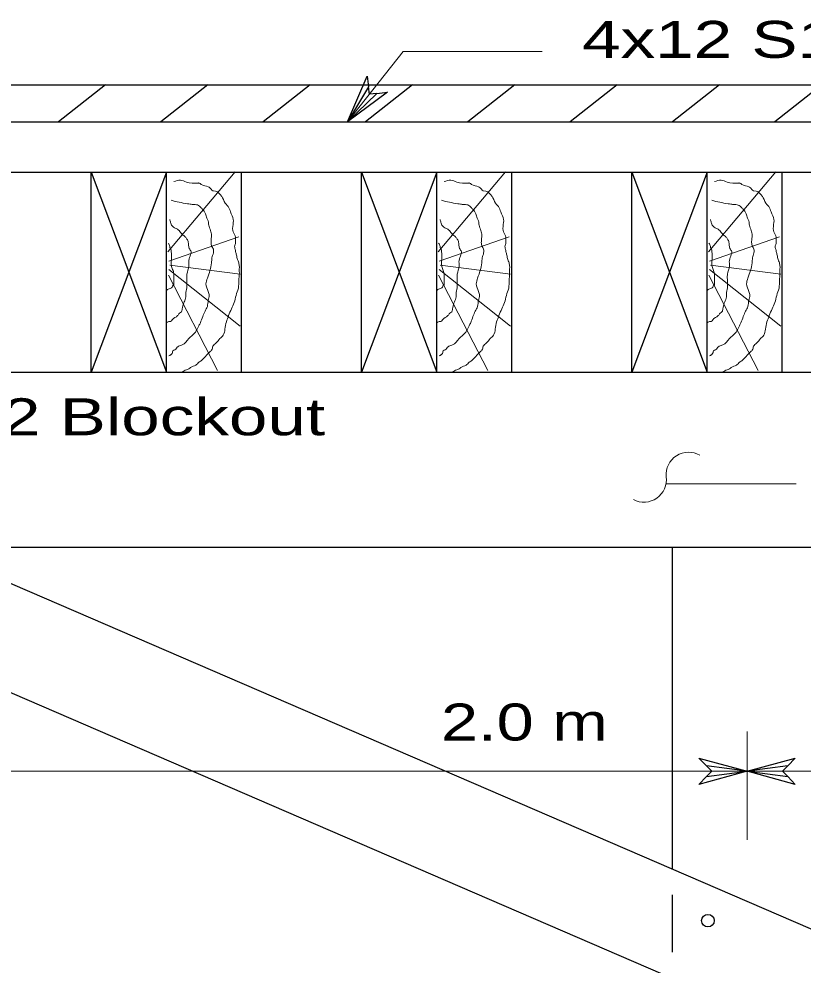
# Model space of a CAD drawing. Extents: x 13426 to 15509, y -9298 to -5111.
# Drawn here: x 15384.27 to 15412, y -5426.77 to -5393.3 of the extents above; entities that cross this region are included whole.
import ezdxf
from ezdxf.enums import TextEntityAlignment as Align

# ---------------------------------------------------------------- set-up
doc = ezdxf.new("R2010")
doc.units = 0
doc.header["$LTSCALE"] = 0.52
for name, color, linetype, lineweight in [('1', 7, 'Continuous', 13), ('15', 7, 'Continuous', 13), ('16', 7, 'Continuous', 25), ('2', 7, 'Continuous', 25), ('20', 7, 'Continuous', 13), ('4', 7, 'Continuous', 13)]:
    doc.layers.add(name, color=color, linetype=linetype, lineweight=lineweight)
doc.layers.add('19', color=7, linetype='Continuous')

msp = doc.modelspace()

# ---------------------------------------------------------------- linework, layer by layer
at = {"layer": '1', "lineweight": 25}
for p, q in [((15363.992, -5405.801), (15491.456, -5405.801)), ((15491.456, -5411.997), (15381.02, -5411.997)), ((15407.365, -5411.997), (15407.365, -5423.373)), ((15407.365, -5424.286), (15407.365, -5426.316))]:
    msp.add_line(p, q, dxfattribs=at)
at = {"layer": '1'}
for p, q in [((15410.021, -5418.508), (15410.021, -5422.337)), ((15374.614, -5419.918), (15410.021, -5419.918))]:
    msp.add_line(p, q, dxfattribs=at)
msp.add_lwpolyline([(15410.021, -5419.918), (15427.724, -5419.918), (15445.428, -5419.918)], dxfattribs=at)
at = {"layer": '15'}
msp.add_line((15407.154, -5409.744), (15411.753, -5409.744), dxfattribs=at)
msp.add_lwpolyline([(15395.887, -5396.949), (15397.859, -5394.453), (15402.777, -5394.453)], dxfattribs=at)
for centre, start, end in [((15407.9489, -5409.4258), 59.84377, 185.31451), ((15406.3728, -5409.6049), 242.17771, 7.64844)]:
    msp.add_arc(centre, 0.7933, start, end, dxfattribs=at)
at = {"layer": '16'}
for points in [[(15396.926, -5395.937), (15397.308, -5395.9), (15395.887, -5396.949), (15396.579, -5395.324), (15396.631, -5395.704), (15395.887, -5396.949), (15396.926, -5395.937), (15396.662, -5395.968), (15396.631, -5395.704)], [(15408.582, -5419.73), (15408.317, -5419.454), (15410.021, -5419.918), (15408.317, -5420.383), (15408.582, -5420.106), (15410.021, -5419.918), (15408.582, -5419.73), (15408.77, -5419.918), (15408.582, -5420.106)], [(15411.459, -5420.106), (15411.725, -5420.383), (15410.021, -5419.918), (15411.725, -5419.454), (15411.459, -5419.73), (15410.021, -5419.918), (15411.459, -5420.106), (15411.271, -5419.918), (15411.459, -5419.73)]]:
    msp.add_lwpolyline(points, dxfattribs=at)
at = {"layer": '2'}
for p, q in [((15366.672, -5405.801), (15490.937, -5459.463)), ((15365.268, -5409.051), (15489.534, -5462.713))]:
    msp.add_line(p, q, dxfattribs=at)
msp.add_circle((15408.6347, -5425.2011), 0.2213, dxfattribs=at)
at = {"layer": '4', "lineweight": 25}
for p, q in [((15368.805, -5395.631), (15486.643, -5395.631)), ((15387.328, -5395.631), (15385.671, -5396.949)), ((15390.947, -5395.631), (15389.29, -5396.949)), ((15394.567, -5395.631), (15392.91, -5396.949)), ((15398.186, -5395.631), (15396.529, -5396.949)), ((15401.806, -5395.631), (15400.149, -5396.949)), ((15405.425, -5395.631), (15403.768, -5396.949)), ((15409.044, -5395.631), (15407.388, -5396.949)), ((15412.664, -5395.631), (15411.007, -5396.949)), ((15369.303, -5398.72), (15486.145, -5398.72)), ((15386.829, -5405.801), (15386.829, -5398.72)), ((15386.829, -5398.72), (15389.485, -5405.801)), ((15389.485, -5398.72), (15386.829, -5405.801)), ((15389.485, -5405.801), (15389.485, -5398.72)), ((15392.14, -5405.801), (15392.14, -5398.72)), ((15396.389, -5405.801), (15396.389, -5398.72)), ((15396.389, -5398.72), (15399.045, -5405.801)), ((15399.045, -5398.72), (15396.389, -5405.801)), ((15399.045, -5405.801), (15399.045, -5398.72)), ((15401.7, -5405.801), (15401.7, -5398.72)), ((15405.949, -5405.801), (15405.949, -5398.72)), ((15405.949, -5398.72), (15408.604, -5405.801)), ((15408.604, -5398.72), (15405.949, -5405.801)), ((15408.604, -5405.801), (15408.604, -5398.72)), ((15411.26, -5405.801), (15411.26, -5398.72))]:
    msp.add_line(p, q, dxfattribs=at)
at = {"layer": '4'}
for p, q in [((15391.916, -5398.719), (15389.537, -5401.539)), ((15401.475, -5398.719), (15399.097, -5401.539)), ((15411.035, -5398.719), (15408.657, -5401.539)), ((15392.047, -5401.013), (15389.57, -5401.879)), ((15401.607, -5401.013), (15399.13, -5401.879)), ((15411.167, -5401.013), (15408.69, -5401.879)), ((15392.096, -5402.337), (15389.603, -5402.015)), ((15401.656, -5402.337), (15399.163, -5402.015)), ((15411.216, -5402.337), (15408.722, -5402.015)), ((15391.292, -5405.735), (15389.553, -5402.372)), ((15392.096, -5404.172), (15389.57, -5402.168)), ((15400.852, -5405.735), (15399.113, -5402.372)), ((15401.656, -5404.172), (15399.13, -5402.168)), ((15410.412, -5405.735), (15408.673, -5402.372)), ((15411.216, -5404.172), (15408.69, -5402.168))]:
    msp.add_line(p, q, dxfattribs=at)
at = {"layer": '4', "lineweight": 25}
msp.add_lwpolyline([(15369.303, -5396.949), (15486.145, -5396.949), (15486.145, -5405.801)], dxfattribs=at)
at = {"layer": '4'}
for points in [[(15389.75, -5399.059), (15389.98, -5399.008), (15390.193, -5399.076), (15390.603, -5399.109), (15390.636, -5399.109), (15390.718, -5399.161), (15390.964, -5399.245), (15391.063, -5399.33), (15391.128, -5399.382), (15391.145, -5399.382), (15391.407, -5399.534), (15391.473, -5399.636), (15391.604, -5399.874), (15391.67, -5399.942), (15391.752, -5400.129), (15391.85, -5400.401), (15391.85, -5400.503), (15391.834, -5400.791), (15391.916, -5400.979), (15391.932, -5401.149), (15391.916, -5401.284), (15391.899, -5401.335), (15391.899, -5401.386), (15391.916, -5401.454), (15391.932, -5401.539), (15391.965, -5401.658), (15391.981, -5401.743), (15392.03, -5401.896), (15392.063, -5402.032), (15392.063, -5402.151), (15392.063, -5402.337), (15392.047, -5402.542), (15392.03, -5402.83), (15391.948, -5403.085), (15391.883, -5403.34), (15391.784, -5403.561), (15391.686, -5403.799), (15391.604, -5404.019), (15391.555, -5404.274), (15391.489, -5404.495), (15391.375, -5404.614), (15391.243, -5404.767), (15391.128, -5404.886), (15391.112, -5404.954), (15391.079, -5405.022), (15391.014, -5405.09), (15390.915, -5405.192), (15390.833, -5405.277), (15390.735, -5405.379), (15390.636, -5405.447), (15390.521, -5405.549), (15390.341, -5405.634), (15390.275, -5405.685), (15390.193, -5405.719), (15390.111, -5405.753), (15389.964, -5405.804), (15389.962, -5405.804)], [(15399.31, -5399.059), (15399.54, -5399.008), (15399.753, -5399.076), (15400.163, -5399.109), (15400.196, -5399.109), (15400.278, -5399.161), (15400.524, -5399.245), (15400.622, -5399.33), (15400.688, -5399.382), (15400.704, -5399.382), (15400.967, -5399.534), (15401.032, -5399.636), (15401.164, -5399.874), (15401.229, -5399.942), (15401.311, -5400.129), (15401.41, -5400.401), (15401.41, -5400.503), (15401.393, -5400.791), (15401.475, -5400.979), (15401.492, -5401.149), (15401.475, -5401.284), (15401.459, -5401.335), (15401.459, -5401.386), (15401.475, -5401.454), (15401.492, -5401.539), (15401.525, -5401.658), (15401.541, -5401.743), (15401.59, -5401.896), (15401.623, -5402.032), (15401.623, -5402.151), (15401.623, -5402.337), (15401.607, -5402.542), (15401.59, -5402.83), (15401.508, -5403.085), (15401.443, -5403.34), (15401.344, -5403.561), (15401.246, -5403.799), (15401.164, -5404.019), (15401.115, -5404.274), (15401.049, -5404.495), (15400.934, -5404.614), (15400.803, -5404.767), (15400.688, -5404.886), (15400.672, -5404.954), (15400.639, -5405.022), (15400.573, -5405.09), (15400.475, -5405.192), (15400.393, -5405.277), (15400.295, -5405.379), (15400.196, -5405.447), (15400.081, -5405.549), (15399.901, -5405.634), (15399.835, -5405.685), (15399.753, -5405.719), (15399.671, -5405.753), (15399.523, -5405.804), (15399.522, -5405.804)], [(15408.87, -5399.059), (15409.1, -5399.008), (15409.313, -5399.076), (15409.723, -5399.109), (15409.756, -5399.109), (15409.838, -5399.161), (15410.084, -5399.245), (15410.182, -5399.33), (15410.248, -5399.382), (15410.264, -5399.382), (15410.527, -5399.534), (15410.592, -5399.636), (15410.724, -5399.874), (15410.789, -5399.942), (15410.871, -5400.129), (15410.97, -5400.401), (15410.97, -5400.503), (15410.953, -5400.791), (15411.035, -5400.979), (15411.052, -5401.149), (15411.035, -5401.284), (15411.019, -5401.335), (15411.019, -5401.386), (15411.035, -5401.454), (15411.052, -5401.539), (15411.084, -5401.658), (15411.101, -5401.743), (15411.15, -5401.896), (15411.183, -5402.032), (15411.183, -5402.151), (15411.183, -5402.337), (15411.167, -5402.542), (15411.15, -5402.83), (15411.068, -5403.085), (15411.003, -5403.34), (15410.904, -5403.561), (15410.806, -5403.799), (15410.724, -5404.019), (15410.674, -5404.274), (15410.609, -5404.495), (15410.494, -5404.614), (15410.363, -5404.767), (15410.248, -5404.886), (15410.231, -5404.954), (15410.199, -5405.022), (15410.133, -5405.09), (15410.035, -5405.192), (15409.953, -5405.277), (15409.854, -5405.379), (15409.756, -5405.447), (15409.641, -5405.549), (15409.461, -5405.634), (15409.395, -5405.685), (15409.313, -5405.719), (15409.231, -5405.753), (15409.083, -5405.804), (15409.082, -5405.804)], [(15389.652, -5399.721), (15389.931, -5399.789), (15390.226, -5399.84), (15390.325, -5399.857), (15390.456, -5399.874), (15390.505, -5399.874), (15390.653, -5399.925), (15390.669, -5399.942), (15390.751, -5400.027), (15390.866, -5400.197), (15390.915, -5400.35), (15390.964, -5400.452), (15390.981, -5400.605), (15391.046, -5400.791), (15391.079, -5400.961), (15391.063, -5401.182), (15391.079, -5401.318), (15391.145, -5401.454), (15391.145, -5401.573), (15391.096, -5401.76), (15391.079, -5401.93), (15390.932, -5402.473), (15390.882, -5402.677), (15390.964, -5402.949), (15390.997, -5403.085), (15390.964, -5403.255), (15390.932, -5403.476), (15390.85, -5403.646), (15390.768, -5403.833), (15390.685, -5404.053), (15390.636, -5404.156), (15390.538, -5404.343), (15390.407, -5404.495), (15390.275, -5404.614), (15390.046, -5404.835), (15389.98, -5404.852), (15389.914, -5404.886), (15389.865, -5404.92), (15389.816, -5404.988), (15389.701, -5405.073), (15389.701, -5405.107), (15389.652, -5405.175), (15389.635, -5405.192), (15389.57, -5405.226)], [(15399.212, -5399.721), (15399.491, -5399.789), (15399.786, -5399.84), (15399.884, -5399.857), (15400.016, -5399.874), (15400.065, -5399.874), (15400.213, -5399.925), (15400.229, -5399.942), (15400.311, -5400.027), (15400.425, -5400.197), (15400.475, -5400.35), (15400.524, -5400.452), (15400.541, -5400.605), (15400.606, -5400.791), (15400.639, -5400.961), (15400.622, -5401.182), (15400.639, -5401.318), (15400.704, -5401.454), (15400.704, -5401.573), (15400.655, -5401.76), (15400.639, -5401.93), (15400.491, -5402.473), (15400.442, -5402.677), (15400.524, -5402.949), (15400.557, -5403.085), (15400.524, -5403.255), (15400.491, -5403.476), (15400.409, -5403.646), (15400.327, -5403.833), (15400.245, -5404.053), (15400.196, -5404.156), (15400.098, -5404.343), (15399.966, -5404.495), (15399.835, -5404.614), (15399.606, -5404.835), (15399.54, -5404.852), (15399.474, -5404.886), (15399.425, -5404.92), (15399.376, -5404.988), (15399.261, -5405.073), (15399.261, -5405.107), (15399.212, -5405.175), (15399.195, -5405.192), (15399.13, -5405.226)], [(15408.772, -5399.721), (15409.051, -5399.789), (15409.346, -5399.84), (15409.444, -5399.857), (15409.575, -5399.874), (15409.625, -5399.874), (15409.772, -5399.925), (15409.789, -5399.942), (15409.871, -5400.027), (15409.985, -5400.197), (15410.035, -5400.35), (15410.084, -5400.452), (15410.101, -5400.605), (15410.166, -5400.791), (15410.199, -5400.961), (15410.182, -5401.182), (15410.199, -5401.318), (15410.264, -5401.454), (15410.264, -5401.573), (15410.215, -5401.76), (15410.199, -5401.93), (15410.051, -5402.473), (15410.002, -5402.677), (15410.084, -5402.949), (15410.117, -5403.085), (15410.084, -5403.255), (15410.051, -5403.476), (15409.969, -5403.646), (15409.887, -5403.833), (15409.805, -5404.053), (15409.756, -5404.156), (15409.658, -5404.343), (15409.526, -5404.495), (15409.395, -5404.614), (15409.165, -5404.835), (15409.1, -5404.852), (15409.034, -5404.886), (15408.985, -5404.92), (15408.936, -5404.988), (15408.821, -5405.073), (15408.821, -5405.107), (15408.772, -5405.175), (15408.755, -5405.192), (15408.69, -5405.226)], [(15389.603, -5400.401), (15389.635, -5400.503), (15389.685, -5400.622), (15389.8, -5400.706), (15389.849, -5400.724), (15389.931, -5400.791), (15390.046, -5400.928), (15390.144, -5401.013), (15390.21, -5401.097), (15390.259, -5401.199), (15390.292, -5401.42), (15390.357, -5401.539), (15390.341, -5401.641), (15390.275, -5401.845), (15390.275, -5402.049), (15390.21, -5402.337), (15390.21, -5402.762), (15390.177, -5402.983), (15390.161, -5403.187), (15390.095, -5403.357), (15390.046, -5403.561), (15390.013, -5403.663), (15389.947, -5403.714), (15389.882, -5403.799), (15389.685, -5403.952), (15389.635, -5404.003), (15389.603, -5404.003), (15389.488, -5404.053)], [(15399.163, -5400.401), (15399.195, -5400.503), (15399.245, -5400.622), (15399.359, -5400.706), (15399.409, -5400.724), (15399.491, -5400.791), (15399.606, -5400.928), (15399.704, -5401.013), (15399.77, -5401.097), (15399.819, -5401.199), (15399.852, -5401.42), (15399.917, -5401.539), (15399.901, -5401.641), (15399.835, -5401.845), (15399.835, -5402.049), (15399.77, -5402.337), (15399.77, -5402.762), (15399.737, -5402.983), (15399.72, -5403.187), (15399.655, -5403.357), (15399.606, -5403.561), (15399.573, -5403.663), (15399.507, -5403.714), (15399.441, -5403.799), (15399.245, -5403.952), (15399.195, -5404.003), (15399.163, -5404.003), (15399.048, -5404.053)], [(15408.722, -5400.401), (15408.755, -5400.503), (15408.804, -5400.622), (15408.919, -5400.706), (15408.969, -5400.724), (15409.051, -5400.791), (15409.165, -5400.928), (15409.264, -5401.013), (15409.329, -5401.097), (15409.379, -5401.199), (15409.411, -5401.42), (15409.477, -5401.539), (15409.461, -5401.641), (15409.395, -5401.845), (15409.395, -5402.049), (15409.329, -5402.337), (15409.329, -5402.762), (15409.297, -5402.983), (15409.28, -5403.187), (15409.215, -5403.357), (15409.165, -5403.561), (15409.133, -5403.663), (15409.067, -5403.714), (15409.001, -5403.799), (15408.804, -5403.952), (15408.755, -5404.003), (15408.722, -5404.003), (15408.608, -5404.053)], [(15389.553, -5401.233), (15389.603, -5401.352), (15389.619, -5401.42), (15389.652, -5401.488), (15389.652, -5401.556), (15389.668, -5401.624), (15389.668, -5401.675), (15389.668, -5401.743), (15389.652, -5401.913), (15389.668, -5402.066), (15389.718, -5402.202), (15389.75, -5402.355), (15389.75, -5402.661), (15389.734, -5402.728), (15389.718, -5402.728), (15389.685, -5402.796), (15389.586, -5402.847), (15389.521, -5402.881), (15389.471, -5402.915)], [(15399.113, -5401.233), (15399.163, -5401.352), (15399.179, -5401.42), (15399.212, -5401.488), (15399.212, -5401.556), (15399.228, -5401.624), (15399.228, -5401.675), (15399.228, -5401.743), (15399.212, -5401.913), (15399.228, -5402.066), (15399.277, -5402.202), (15399.31, -5402.355), (15399.31, -5402.661), (15399.294, -5402.728), (15399.277, -5402.728), (15399.245, -5402.796), (15399.146, -5402.847), (15399.08, -5402.881), (15399.031, -5402.915)], [(15408.673, -5401.233), (15408.722, -5401.352), (15408.739, -5401.42), (15408.772, -5401.488), (15408.772, -5401.556), (15408.788, -5401.624), (15408.788, -5401.675), (15408.788, -5401.743), (15408.772, -5401.913), (15408.788, -5402.066), (15408.837, -5402.202), (15408.87, -5402.355), (15408.87, -5402.661), (15408.854, -5402.728), (15408.837, -5402.728), (15408.804, -5402.796), (15408.706, -5402.847), (15408.64, -5402.881), (15408.591, -5402.915)]]:
    msp.add_spline(points, degree=3, dxfattribs=at)

# ---------------------------------------------------------------- texts
at = {"layer": '19', "width": 1.35}
msp.add_text('2.0 m', height=1.307, dxfattribs=at).set_placement((15402.1445, -5418.829), align=Align.CENTER)
at = {"layer": '20', "width": 1.4}
msp.add_text('4x12 S1S Plank deck', height=1.307, dxfattribs=at).set_placement((15415.8165, -5394.681), align=Align.CENTER)
msp.add_text('4x12 Blockout', height=1.307, dxfattribs=at).set_placement((15379.726, -5408.032))

doc.saveas('drawing.dxf')
